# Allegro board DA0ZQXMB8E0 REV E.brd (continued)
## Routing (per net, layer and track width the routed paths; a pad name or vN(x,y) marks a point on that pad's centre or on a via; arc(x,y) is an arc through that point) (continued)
N106400512: length 1.3
  TOP w0.635: PC35.1 91.84,74.91 93.03,74.91 PR73.2
N107846466: length 5.3
  TOP w0.102: TP41.1 115.31,92.1 116.02,91.39 v1(118.33,91.39)
  BOTTOM w0.102: v1(118.33,91.39) 118.9,90.82 119.11,90.82
N107846468: length 7.4
  TOP w0.102: v1(117.56,92.01) 117.03,92.01 116.07,92.97 116.07,93.37 115.31,94.13 TP40.1
  BOTTOM w0.102: 119.75,90.47 118.64,90.47 117.56,91.54 v1(117.56,92.01)
N108094032: length 0.7
  BOTTOM w0.203: PC111.2 210.95,148.12 211.19,148.36
N108094154: length 1
  BOTTOM w0.305: PD9.2 218.94,158.52
N108094465: length 1.6
  TOP w0.102: PR123.2 56.71,46.94 57.24,47.47
N108094467: length 0.4
  BOTTOM w0.203: 52.67,46.75 52.25,46.75
N108099073: length 1.7
  TOP w0.305: PQ30.3 69.49,50.95 PR118.1
N108306483: length 1
  BOTTOM w0.102: R433.1 R434.1
N108322898: length 1
  BOTTOM w0.102: R432.1 R431.1
N108460590: length 1.6
  TOP w0.102: TP39.1 139.21,96.54 v1(138.48,95.82)
  BOTTOM w0.102: v1(138.48,95.82) 138.16,96.14 U28.AP8
N108460599: length 3.7
  TOP w0.102: TP37.1 141.55,96.8 141.09,96.34 140.1,96.34 139.57,95.82 v1(139.13,95.82)
  BOTTOM w0.102: v1(139.13,95.82) 138.81,96.14 U28.AR8
N108615240: length 1.4
  BOTTOM w0.076: 122.22,101.05 122.22,100.74 122.18,100.7 122.18,100.26 U28.F2
N109805540: length 1
  BOTTOM w0.254: 134.98,115.97 134.71,116.23 PQ44.2

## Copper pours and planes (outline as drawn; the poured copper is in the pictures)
+V1.05S_AIDLE on IN2 (solid shape): outline of 340 points within 118.52,95.79 127.55,101.78
+V1.05S_APLLOPI on TOP (solid shape): 102.18,99.37 102.21,99.35 102.23,99.32 102.23,93.75 102.99,92.99 104,92.99 105.31,91.68 105.31,91.33 104.82,90.83 104.53,90.83 103.74,91.62 102,91.62 101.79,91.82 101.79,92.51 100.96,93.35 100.96,99.26 101.06,99.37
+V1.05S_APLLOPI on BOTTOM (solid shape): 130.19,89.04 130.24,89.05 130.7,89.05 130.91,88.83 130.91,88.2 130.89,88.18 130.8,88.12 130.74,88.04 130.73,88.03 130.71,88.01 130.48,88.01 130.46,88.03 130.45,88.04 130.19,88.2 129.93,88.04 129.91,88.02 129.88,88.01 129.68,88.01 129.6,88.09 129.58,88.11 129.48,88.21 129.48,88.85 129.68,89.05 130.14,89.05
+V1.05S_APLLOPI on IN2 (solid shape): outline of 513 points within 104.21,87.38 131.44,92.92
+V3.3S_VCCPCORE on BOTTOM (solid shape): 129.49,96.01 129.5,96.01 129.52,96 129.65,95.91 129.82,95.89 129.83,95.89 129.85,95.88 129.91,95.83 129.91,94.81 130,94.72 130,94.4 129.86,94.26 129.6,94.26 129.45,94.42 129.45,94.69 129.56,94.79 129.56,95.28 129.08,95.75 129.08,95.99 129.1,96.03 129.18,96.11 129.4,96.11
+V3.3S_VCCPCORE on IN3 (solid shape): 125.36,97.48 125.26,97.73 125.68,97.69 125.57,97.43 125.66,97.18 125.69,97.1 125.56,96.79 125.69,96.47 125.66,96.4 125.92,95.8 126.18,96.4 126.15,96.47 126.28,96.79 126.18,97.03 128.74,94.73 128.64,94.74 128.55,94.73 127.85,94.73 127.75,94.74 127.66,94.73 126.96,94.73 126.86,94.74 126.77,94.73 126.51,94.73 125.21,96.03 125.2,96.05 125.21,96.07 125.21,96.2 125.16,96.33 125.13,96.37 125.08,96.43 125.08,96.47 125.11,96.5 125.35,96.75 125.26,97.09 125.23,97.16
+V3.3S_VCCPCORE on IN3 (solid shape): outline of 321 points within 111.68,98.07 124.39,103.3
671_BST on BOTTOM (solid shape): 57.65,46.81 57.65,46.15 57.55,46.05 57.12,46.05 56.84,46.05 56.25,46.64 55.92,46.64 55.92,46.65 55.26,46.65 55.23,46.66 55.21,46.7 55.21,46.81 55.23,46.85 55.26,46.86 57.6,46.86
671_BST1 on BOTTOM (solid shape): 59.06,48 59.06,46.12 59,46.05 58.28,46.05 58.2,46.14 58.2,47.97 58.28,48.06 59,48.06
671_SW on TOP (solid shape): 57.04,54.74 57.04,47.91 56.9,47.77 55.05,47.77 55.03,47.75 54.99,47.75 54.98,47.75 52.99,47.75 52.84,47.91 52.84,48.4 52.82,48.41 52.82,53.14 54.5,54.81 56.96,54.81
671_SW on BOTTOM (solid shape): 57.62,54.64 57.62,47.27 57.57,47.22 55.16,47.22 54.91,46.97 54.91,45.82 54.7,45.62 54.23,45.62 54.21,45.63 54.19,45.64 54.18,45.67 54.18,46.28 53.79,46.28 53.79,45.67 53.78,45.64 53.76,45.63 53.73,45.62 53.33,45.62 53.19,45.76 53.19,46.65 54.19,46.65 54.19,47.75 53.7,47.75 53.7,46.65 53.19,46.65 53.19,46.88 53.13,46.94 53.13,46.95 53.11,46.95 52.81,47.26 52.81,53.18 54.4,54.76 57.5,54.76
+SMDDR_VREF_DQ1 on TOP (solid shape): 162.68,50.32 163.69,50.32 163.82,50.19 163.82,48.67 163.69,48.54 159.76,48.54 159.5,48.8 159.5,50.83 159.63,50.95 162.04,50.95
+SMDDR_VREF_DQ1 on BOTTOM (solid shape): 162.81,50.45 162.81,49.43 162.68,49.3 160.27,49.3 160.01,49.56 160.01,50.57 160.14,50.7 162.55,50.7
CCD_PWR on BOTTOM (solid shape): 77.84,150.47 77.84,150.14 77.6,149.9 77.6,148.5 77.58,148.49 77.35,148.49 77.34,148.5 77.34,149.7 77.32,149.72 77.12,149.72 77.1,149.7 77.1,148.5 77.08,148.48 76.86,148.48 76.84,148.5 76.84,149.84 76.67,150 76.67,150.52 76.78,150.62 77.69,150.62
HDMI_5V on IN2 (solid shape): 15.64,38.66 15.64,37.24 15.28,36.88 12.44,36.88 9.8,34.24 8.96,34.24 8.86,34.34 8.86,35.82 11.9,38.86 15.43,38.86
LCDVCC on BOTTOM (solid shape): 76.59,149.65 76.59,148.45 77.13,147.92 77.13,147.19 76.93,146.99 76.33,148.48 76.34,148.5 76.34,149.66 76.4,149.72 76.52,149.72
R_SPK+_1 on BOTTOM (solid shape): 210.84,49.68 210.84,48.82 210.53,48.51 210.53,46.74 210.33,46.53 210.07,46.53 209.71,49.6 209.87,49.76 210.76,49.76
R_SPK-_1 on BOTTOM (solid shape): 209.32,49.66 209.32,47.18 208.55,47.5 208.55,48.29 208.07,48.77 208.07,49.66 208.18,49.77 209.21,49.77
VA1 on TOP (solid shape): 232.28,115.34 232.28,106.94 231.94,106.61 228.95,106.61 228.62,106.28 226.31,106.28 226.14,106.44 226.14,109.26 226.91,110.03 227.63,110.03 228.72,111.13 228.72,115.34 228.97,115.6 232.02,115.6
VA1 on BOTTOM (solid shape): 232.23,113.62 232.26,113.6 232.28,113.57 232.28,105.85 232.2,105.77 230.14,105.77 229.91,105.54 229.91,105.53 229.85,105.47 229.85,104.25 226.48,104.07 226.33,104.22 226.33,109.53 226.84,110.03 227.63,110.03 228.29,110.69 228.29,113.34 228.57,113.62
VA2 on TOP (solid shape): 231.99,103.56 231.99,98.66 231.77,98.43 226.15,98.43 226.15,100.41 227.58,101.83 227.58,103.56 228.11,104.09 231.46,104.09
VA2 on BOTTOM (solid shape): 232.07,103.02 232.07,97.66 231.64,97.23 226.97,97.23 225.86,98.34 225.86,103.14 226.03,103.3 231.79,103.3
N243495 on BOTTOM (solid shape): 232.12,96.22 232.12,91.82 231.49,91.19 228.79,91.19 228.36,90.76 227.93,90.76 226.74,96.34 226.81,96.42 231.92,96.42
N16780395 on TOP (solid shape): 225.7,81.74 225.7,80.95 225.62,80.88 223.59,80.88 224.81,81.79 225.64,81.79
N16789555 on TOP (solid shape): 64.66,45.49 64.66,45.26 61.94,46 61.94,46.79 62.03,46.88 63.28,46.88
N16789557 on BOTTOM (solid shape): 68.7,53.8 68.7,47.86 68.5,47.65 66.89,47.65 66.18,46.94 66.18,46.23 65.94,45.99 64.01,45.99 68.52,53.98
N19870274 on TOP (solid shape): 52.32,59.34 52.32,57.81 52.06,57.56 42.03,57.56 41.93,57.66 41.93,59.26 42.09,59.43 52.23,59.43

Small or netless copper shapes (teardrops, artwork), in the pictures only: 1 on TOP, 3 on BOTTOM, 5 on IN3
